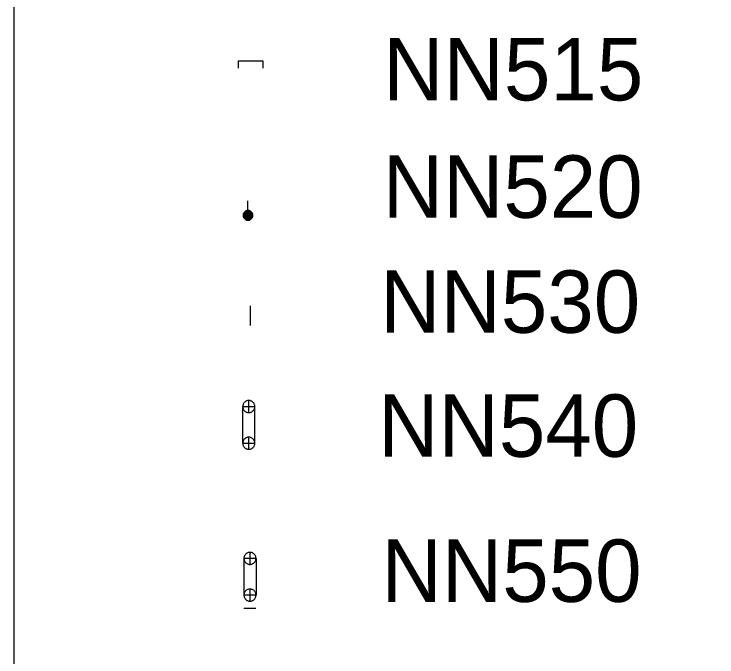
# Model space of a CAD drawing. Extents: x -592841 to -592404, y -1153473 to -1153230.
# Drawn here: x -592679.08 to -592662.21, y -1153397.39 to -1153381.94 of the extents above; entities that cross this region are included whole.
import ezdxf

# ---------------------------------------------------------------- set-up
doc = ezdxf.new("R2010")
doc.units = 0
doc.layers.add('Vrstva 43', color=7, linetype='Continuous')
doc.layers.add('Vrstva 63', color=7, linetype='Continuous')

msp = doc.modelspace()

# ---------------------------------------------------------------- linework, layer by layer
at = {"layer": 'Vrstva 43'}
for points in [[(-592673.703, -1153383.058), (-592673.112, -1153383.058)], [(-592673.703, -1153383.058), (-592673.703, -1153383.235)], [(-592673.112, -1153383.058), (-592673.113, -1153383.236)], [(-592673.468, -1153386.656), (-592673.468, -1153386.421)], [(-592673.351, -1153386.774), (-592673.351, -1153386.761), (-592673.353, -1153386.749), (-592673.357, -1153386.737), (-592673.361, -1153386.726), (-592673.366, -1153386.715), (-592673.373, -1153386.704), (-592673.381, -1153386.695), (-592673.389, -1153386.686), (-592673.399, -1153386.678), (-592673.409, -1153386.672), (-592673.42, -1153386.666), (-592673.431, -1153386.662), (-592673.443, -1153386.658), (-592673.455, -1153386.656), (-592673.468, -1153386.656), (-592673.481, -1153386.656), (-592673.493, -1153386.658), (-592673.505, -1153386.662), (-592673.516, -1153386.666), (-592673.527, -1153386.672), (-592673.537, -1153386.678), (-592673.547, -1153386.686), (-592673.555, -1153386.695), (-592673.563, -1153386.704), (-592673.571, -1153386.715), (-592673.575, -1153386.726), (-592673.58, -1153386.738), (-592673.583, -1153386.749), (-592673.585, -1153386.761), (-592673.585, -1153386.774), (-592673.585, -1153386.786), (-592673.583, -1153386.798), (-592673.58, -1153386.81), (-592673.575, -1153386.822), (-592673.57, -1153386.832), (-592673.563, -1153386.842), (-592673.555, -1153386.852), (-592673.547, -1153386.861), (-592673.537, -1153386.868), (-592673.527, -1153386.876), (-592673.516, -1153386.881), (-592673.505, -1153386.886), (-592673.493, -1153386.888), (-592673.481, -1153386.89), (-592673.468, -1153386.891), (-592673.455, -1153386.891), (-592673.443, -1153386.888), (-592673.431, -1153386.886), (-592673.42, -1153386.881), (-592673.409, -1153386.876), (-592673.399, -1153386.868), (-592673.389, -1153386.861), (-592673.381, -1153386.852), (-592673.373, -1153386.842), (-592673.366, -1153386.833), (-592673.361, -1153386.822), (-592673.357, -1153386.81), (-592673.353, -1153386.798), (-592673.351, -1153386.786), (-592673.351, -1153386.774)], [(-592673.351, -1153386.774), (-592673.351, -1153386.761), (-592673.353, -1153386.749), (-592673.357, -1153386.737), (-592673.361, -1153386.726), (-592673.366, -1153386.715), (-592673.373, -1153386.704), (-592673.381, -1153386.695), (-592673.389, -1153386.686), (-592673.399, -1153386.678), (-592673.409, -1153386.672), (-592673.42, -1153386.666), (-592673.431, -1153386.662), (-592673.443, -1153386.658), (-592673.455, -1153386.656), (-592673.468, -1153386.656), (-592673.481, -1153386.656), (-592673.493, -1153386.658), (-592673.505, -1153386.662), (-592673.516, -1153386.666), (-592673.527, -1153386.672), (-592673.537, -1153386.678), (-592673.547, -1153386.686), (-592673.555, -1153386.695), (-592673.563, -1153386.704), (-592673.571, -1153386.715), (-592673.575, -1153386.726), (-592673.58, -1153386.738), (-592673.583, -1153386.749), (-592673.585, -1153386.761), (-592673.585, -1153386.774), (-592673.585, -1153386.786), (-592673.583, -1153386.798), (-592673.58, -1153386.81), (-592673.575, -1153386.822), (-592673.57, -1153386.832), (-592673.563, -1153386.842), (-592673.555, -1153386.852), (-592673.547, -1153386.861), (-592673.537, -1153386.868), (-592673.527, -1153386.876), (-592673.516, -1153386.881), (-592673.505, -1153386.886), (-592673.493, -1153386.888), (-592673.481, -1153386.89), (-592673.468, -1153386.891), (-592673.455, -1153386.891), (-592673.443, -1153386.888), (-592673.431, -1153386.886), (-592673.42, -1153386.881), (-592673.409, -1153386.876), (-592673.399, -1153386.868), (-592673.389, -1153386.861), (-592673.381, -1153386.852), (-592673.373, -1153386.842), (-592673.366, -1153386.833), (-592673.361, -1153386.822), (-592673.357, -1153386.81), (-592673.353, -1153386.798), (-592673.351, -1153386.786), (-592673.351, -1153386.774)], [(-592673.365, -1153386.774), (-592673.366, -1153386.763), (-592673.367, -1153386.752), (-592673.371, -1153386.742), (-592673.374, -1153386.732), (-592673.379, -1153386.722), (-592673.385, -1153386.713), (-592673.391, -1153386.705), (-592673.399, -1153386.697), (-592673.407, -1153386.69), (-592673.417, -1153386.684), (-592673.426, -1153386.68), (-592673.437, -1153386.676), (-592673.447, -1153386.673), (-592673.457, -1153386.672), (-592673.468, -1153386.671), (-592673.479, -1153386.672), (-592673.49, -1153386.673), (-592673.5, -1153386.676), (-592673.51, -1153386.68), (-592673.519, -1153386.684), (-592673.529, -1153386.691), (-592673.537, -1153386.697), (-592673.545, -1153386.705), (-592673.551, -1153386.713), (-592673.557, -1153386.722), (-592673.563, -1153386.732), (-592673.565, -1153386.742), (-592673.569, -1153386.752), (-592673.57, -1153386.763), (-592673.571, -1153386.774), (-592673.57, -1153386.784), (-592673.569, -1153386.795), (-592673.565, -1153386.806), (-592673.563, -1153386.816), (-592673.557, -1153386.826), (-592673.551, -1153386.834), (-592673.545, -1153386.842), (-592673.537, -1153386.85), (-592673.529, -1153386.857), (-592673.519, -1153386.862), (-592673.51, -1153386.868), (-592673.5, -1153386.871), (-592673.489, -1153386.874), (-592673.479, -1153386.876), (-592673.468, -1153386.876), (-592673.458, -1153386.876), (-592673.447, -1153386.874), (-592673.437, -1153386.871), (-592673.426, -1153386.868), (-592673.417, -1153386.862), (-592673.407, -1153386.856), (-592673.399, -1153386.85), (-592673.391, -1153386.842), (-592673.385, -1153386.834), (-592673.379, -1153386.825), (-592673.374, -1153386.816), (-592673.371, -1153386.806), (-592673.368, -1153386.795), (-592673.367, -1153386.784), (-592673.365, -1153386.774)], [(-592673.38, -1153386.774), (-592673.381, -1153386.764), (-592673.382, -1153386.755), (-592673.385, -1153386.746), (-592673.387, -1153386.738), (-592673.393, -1153386.73), (-592673.397, -1153386.722), (-592673.403, -1153386.714), (-592673.409, -1153386.708), (-592673.417, -1153386.703), (-592673.425, -1153386.698), (-592673.433, -1153386.693), (-592673.441, -1153386.69), (-592673.449, -1153386.688), (-592673.459, -1153386.686), (-592673.469, -1153386.686), (-592673.477, -1153386.686), (-592673.487, -1153386.688), (-592673.495, -1153386.69), (-592673.504, -1153386.693), (-592673.512, -1153386.698), (-592673.519, -1153386.702), (-592673.527, -1153386.708), (-592673.533, -1153386.714), (-592673.539, -1153386.722), (-592673.544, -1153386.73), (-592673.549, -1153386.738), (-592673.551, -1153386.746), (-592673.554, -1153386.755), (-592673.555, -1153386.764), (-592673.556, -1153386.774), (-592673.555, -1153386.783), (-592673.554, -1153386.792), (-592673.551, -1153386.8), (-592673.549, -1153386.81), (-592673.545, -1153386.818), (-592673.539, -1153386.825), (-592673.533, -1153386.832), (-592673.527, -1153386.839), (-592673.519, -1153386.845), (-592673.512, -1153386.85), (-592673.504, -1153386.854), (-592673.495, -1153386.857), (-592673.487, -1153386.86), (-592673.477, -1153386.861), (-592673.469, -1153386.862), (-592673.459, -1153386.861), (-592673.449, -1153386.86), (-592673.441, -1153386.857), (-592673.433, -1153386.854), (-592673.424, -1153386.85), (-592673.417, -1153386.844), (-592673.409, -1153386.839), (-592673.403, -1153386.832), (-592673.397, -1153386.825), (-592673.392, -1153386.818), (-592673.387, -1153386.81), (-592673.385, -1153386.8), (-592673.382, -1153386.792), (-592673.381, -1153386.782), (-592673.38, -1153386.774)], [(-592673.395, -1153386.774), (-592673.396, -1153386.766), (-592673.397, -1153386.758), (-592673.399, -1153386.751), (-592673.401, -1153386.744), (-592673.405, -1153386.737), (-592673.409, -1153386.73), (-592673.414, -1153386.724), (-592673.419, -1153386.719), (-592673.425, -1153386.714), (-592673.432, -1153386.71), (-592673.439, -1153386.706), (-592673.445, -1153386.704), (-592673.453, -1153386.702), (-592673.461, -1153386.701), (-592673.468, -1153386.7), (-592673.475, -1153386.701), (-592673.483, -1153386.702), (-592673.491, -1153386.704), (-592673.497, -1153386.706), (-592673.505, -1153386.71), (-592673.511, -1153386.714), (-592673.517, -1153386.719), (-592673.523, -1153386.724), (-592673.527, -1153386.731), (-592673.532, -1153386.737), (-592673.535, -1153386.744), (-592673.537, -1153386.751), (-592673.539, -1153386.758), (-592673.541, -1153386.766), (-592673.541, -1153386.774), (-592673.541, -1153386.781), (-592673.539, -1153386.788), (-592673.537, -1153386.796), (-592673.535, -1153386.803), (-592673.531, -1153386.81), (-592673.527, -1153386.816), (-592673.523, -1153386.823), (-592673.517, -1153386.828), (-592673.511, -1153386.832), (-592673.505, -1153386.837), (-592673.497, -1153386.84), (-592673.491, -1153386.843), (-592673.483, -1153386.845), (-592673.475, -1153386.846), (-592673.468, -1153386.846), (-592673.461, -1153386.846), (-592673.453, -1153386.845), (-592673.445, -1153386.843), (-592673.439, -1153386.84), (-592673.431, -1153386.837), (-592673.425, -1153386.832), (-592673.419, -1153386.828), (-592673.413, -1153386.822), (-592673.409, -1153386.816), (-592673.405, -1153386.81), (-592673.401, -1153386.803), (-592673.399, -1153386.796), (-592673.397, -1153386.788), (-592673.395, -1153386.781), (-592673.395, -1153386.774)], [(-592673.409, -1153386.774), (-592673.41, -1153386.768), (-592673.411, -1153386.762), (-592673.413, -1153386.756), (-592673.415, -1153386.75), (-592673.417, -1153386.744), (-592673.421, -1153386.739), (-592673.425, -1153386.734), (-592673.429, -1153386.73), (-592673.433, -1153386.726), (-592673.439, -1153386.723), (-592673.445, -1153386.721), (-592673.45, -1153386.718), (-592673.456, -1153386.716), (-592673.462, -1153386.716), (-592673.468, -1153386.715), (-592673.474, -1153386.716), (-592673.48, -1153386.716), (-592673.487, -1153386.718), (-592673.491, -1153386.72), (-592673.497, -1153386.723), (-592673.503, -1153386.726), (-592673.507, -1153386.73), (-592673.511, -1153386.735), (-592673.515, -1153386.739), (-592673.519, -1153386.744), (-592673.521, -1153386.75), (-592673.523, -1153386.756), (-592673.525, -1153386.762), (-592673.526, -1153386.768), (-592673.527, -1153386.774), (-592673.526, -1153386.78), (-592673.525, -1153386.786), (-592673.523, -1153386.792), (-592673.521, -1153386.797), (-592673.519, -1153386.802), (-592673.515, -1153386.808), (-592673.512, -1153386.812), (-592673.507, -1153386.817), (-592673.503, -1153386.82), (-592673.497, -1153386.824), (-592673.491, -1153386.827), (-592673.486, -1153386.829), (-592673.48, -1153386.83), (-592673.474, -1153386.832), (-592673.468, -1153386.832), (-592673.462, -1153386.832), (-592673.456, -1153386.83), (-592673.451, -1153386.829), (-592673.445, -1153386.827), (-592673.439, -1153386.824), (-592673.433, -1153386.82), (-592673.429, -1153386.817), (-592673.425, -1153386.812), (-592673.421, -1153386.808), (-592673.417, -1153386.802), (-592673.415, -1153386.798), (-592673.413, -1153386.792), (-592673.411, -1153386.786), (-592673.41, -1153386.78), (-592673.409, -1153386.774)], [(-592673.425, -1153386.774), (-592673.425, -1153386.769), (-592673.425, -1153386.764), (-592673.427, -1153386.76), (-592673.429, -1153386.756), (-592673.431, -1153386.752), (-592673.433, -1153386.748), (-592673.435, -1153386.744), (-592673.439, -1153386.741), (-592673.443, -1153386.738), (-592673.447, -1153386.736), (-592673.451, -1153386.734), (-592673.455, -1153386.732), (-592673.459, -1153386.731), (-592673.464, -1153386.73), (-592673.469, -1153386.73), (-592673.473, -1153386.73), (-592673.477, -1153386.732), (-592673.481, -1153386.732), (-592673.485, -1153386.734), (-592673.49, -1153386.736), (-592673.493, -1153386.739), (-592673.497, -1153386.741), (-592673.501, -1153386.744), (-592673.503, -1153386.748), (-592673.505, -1153386.752), (-592673.507, -1153386.756), (-592673.51, -1153386.76), (-592673.511, -1153386.764), (-592673.511, -1153386.769), (-592673.511, -1153386.774), (-592673.511, -1153386.778), (-592673.511, -1153386.782), (-592673.509, -1153386.787), (-592673.507, -1153386.791), (-592673.505, -1153386.795), (-592673.503, -1153386.799), (-592673.501, -1153386.802), (-592673.497, -1153386.806), (-592673.493, -1153386.808), (-592673.489, -1153386.811), (-592673.485, -1153386.813), (-592673.481, -1153386.815), (-592673.477, -1153386.816), (-592673.473, -1153386.817), (-592673.468, -1153386.817), (-592673.463, -1153386.817), (-592673.459, -1153386.816), (-592673.455, -1153386.815), (-592673.451, -1153386.813), (-592673.447, -1153386.811), (-592673.443, -1153386.808), (-592673.439, -1153386.806), (-592673.435, -1153386.802), (-592673.433, -1153386.799), (-592673.431, -1153386.795), (-592673.429, -1153386.791), (-592673.427, -1153386.787), (-592673.425, -1153386.782), (-592673.425, -1153386.778), (-592673.425, -1153386.774)], [(-592673.439, -1153386.774), (-592673.439, -1153386.77), (-592673.44, -1153386.768), (-592673.441, -1153386.764), (-592673.442, -1153386.762), (-592673.443, -1153386.76), (-592673.445, -1153386.756), (-592673.447, -1153386.754), (-592673.449, -1153386.752), (-592673.451, -1153386.75), (-592673.453, -1153386.748), (-592673.457, -1153386.748), (-592673.459, -1153386.746), (-592673.462, -1153386.746), (-592673.465, -1153386.745), (-592673.468, -1153386.745), (-592673.471, -1153386.745), (-592673.474, -1153386.746), (-592673.477, -1153386.746), (-592673.48, -1153386.748), (-592673.483, -1153386.748), (-592673.485, -1153386.75), (-592673.487, -1153386.752), (-592673.489, -1153386.754), (-592673.491, -1153386.756), (-592673.493, -1153386.759), (-592673.494, -1153386.762), (-592673.495, -1153386.764), (-592673.496, -1153386.768), (-592673.497, -1153386.771), (-592673.497, -1153386.774), (-592673.497, -1153386.776), (-592673.496, -1153386.78), (-592673.496, -1153386.782), (-592673.494, -1153386.785), (-592673.493, -1153386.788), (-592673.491, -1153386.79), (-592673.489, -1153386.792), (-592673.487, -1153386.795), (-592673.485, -1153386.796), (-592673.483, -1153386.798), (-592673.479, -1153386.8), (-592673.477, -1153386.801), (-592673.474, -1153386.802), (-592673.471, -1153386.802), (-592673.468, -1153386.802), (-592673.465, -1153386.802), (-592673.463, -1153386.802), (-592673.459, -1153386.801), (-592673.457, -1153386.8), (-592673.453, -1153386.798), (-592673.451, -1153386.796), (-592673.449, -1153386.795), (-592673.447, -1153386.792), (-592673.445, -1153386.79), (-592673.443, -1153386.788), (-592673.442, -1153386.785), (-592673.441, -1153386.782), (-592673.44, -1153386.78), (-592673.439, -1153386.776), (-592673.439, -1153386.774)], [(-592673.455, -1153386.774), (-592673.454, -1153386.772), (-592673.455, -1153386.77), (-592673.455, -1153386.769), (-592673.456, -1153386.768), (-592673.456, -1153386.766), (-592673.457, -1153386.766), (-592673.457, -1153386.764), (-592673.459, -1153386.763), (-592673.461, -1153386.762), (-592673.461, -1153386.762), (-592673.463, -1153386.761), (-592673.463, -1153386.76), (-592673.465, -1153386.76), (-592673.467, -1153386.76), (-592673.468, -1153386.76), (-592673.469, -1153386.76), (-592673.471, -1153386.76), (-592673.473, -1153386.76), (-592673.474, -1153386.761), (-592673.475, -1153386.762), (-592673.476, -1153386.762), (-592673.478, -1153386.763), (-592673.479, -1153386.764), (-592673.479, -1153386.766), (-592673.48, -1153386.766), (-592673.481, -1153386.768), (-592673.481, -1153386.769), (-592673.482, -1153386.77), (-592673.482, -1153386.772), (-592673.483, -1153386.774), (-592673.482, -1153386.775), (-592673.481, -1153386.777), (-592673.481, -1153386.778), (-592673.481, -1153386.779), (-592673.48, -1153386.78), (-592673.479, -1153386.782), (-592673.479, -1153386.783), (-592673.478, -1153386.784), (-592673.477, -1153386.784), (-592673.475, -1153386.786), (-592673.473, -1153386.786), (-592673.473, -1153386.786), (-592673.471, -1153386.787), (-592673.47, -1153386.788), (-592673.468, -1153386.788), (-592673.467, -1153386.788), (-592673.465, -1153386.787), (-592673.463, -1153386.786), (-592673.463, -1153386.786), (-592673.461, -1153386.786), (-592673.46, -1153386.784), (-592673.459, -1153386.784), (-592673.457, -1153386.783), (-592673.457, -1153386.782), (-592673.456, -1153386.78), (-592673.455, -1153386.78), (-592673.455, -1153386.778), (-592673.455, -1153386.776), (-592673.454, -1153386.775), (-592673.455, -1153386.774)], [(-592673.411, -1153389.419), (-592673.411, -1153388.951)], [(-592673.595, -1153391.368), (-592673.593, -1153391.384), (-592673.591, -1153391.4), (-592673.587, -1153391.414), (-592673.582, -1153391.428), (-592673.575, -1153391.442), (-592673.567, -1153391.454), (-592673.557, -1153391.466), (-592673.546, -1153391.478), (-592673.535, -1153391.488), (-592673.522, -1153391.495), (-592673.509, -1153391.502), (-592673.493, -1153391.507), (-592673.479, -1153391.512), (-592673.465, -1153391.514), (-592673.449, -1153391.515), (-592673.434, -1153391.514), (-592673.419, -1153391.512), (-592673.404, -1153391.508), (-592673.389, -1153391.502), (-592673.376, -1153391.495), (-592673.364, -1153391.486), (-592673.351, -1153391.477), (-592673.341, -1153391.466), (-592673.331, -1153391.454), (-592673.323, -1153391.442), (-592673.317, -1153391.429), (-592673.311, -1153391.414), (-592673.307, -1153391.399), (-592673.305, -1153391.384), (-592673.304, -1153391.37), (-592673.304, -1153391.354), (-592673.307, -1153391.339), (-592673.311, -1153391.324), (-592673.317, -1153391.31), (-592673.323, -1153391.296), (-592673.331, -1153391.283), (-592673.341, -1153391.272), (-592673.351, -1153391.261), (-592673.363, -1153391.252), (-592673.376, -1153391.243), (-592673.389, -1153391.236), (-592673.405, -1153391.23), (-592673.419, -1153391.227), (-592673.434, -1153391.224), (-592673.449, -1153391.224), (-592673.465, -1153391.224), (-592673.479, -1153391.227), (-592673.493, -1153391.231), (-592673.509, -1153391.236), (-592673.521, -1153391.243), (-592673.535, -1153391.252), (-592673.547, -1153391.26), (-592673.557, -1153391.272), (-592673.567, -1153391.284), (-592673.575, -1153391.297), (-592673.582, -1153391.31), (-592673.587, -1153391.324), (-592673.591, -1153391.339), (-592673.594, -1153391.354), (-592673.595, -1153391.368)], [(-592673.595, -1153391.368), (-592673.304, -1153391.37)], [(-592673.595, -1153392.251), (-592673.595, -1153391.368)], [(-592673.449, -1153391.515), (-592673.449, -1153391.224)], [(-592673.303, -1153392.251), (-592673.304, -1153391.37)], [(-592673.595, -1153392.251), (-592673.593, -1153392.266), (-592673.591, -1153392.282), (-592673.587, -1153392.296), (-592673.582, -1153392.31), (-592673.575, -1153392.324), (-592673.567, -1153392.336), (-592673.557, -1153392.348), (-592673.546, -1153392.36), (-592673.535, -1153392.368), (-592673.521, -1153392.378), (-592673.509, -1153392.384), (-592673.494, -1153392.389), (-592673.479, -1153392.394), (-592673.465, -1153392.396), (-592673.449, -1153392.397), (-592673.433, -1153392.396), (-592673.419, -1153392.394), (-592673.405, -1153392.39), (-592673.389, -1153392.384), (-592673.376, -1153392.377), (-592673.364, -1153392.368), (-592673.352, -1153392.358), (-592673.341, -1153392.348), (-592673.331, -1153392.337), (-592673.323, -1153392.324), (-592673.316, -1153392.31), (-592673.311, -1153392.296), (-592673.307, -1153392.28), (-592673.305, -1153392.266), (-592673.303, -1153392.251), (-592673.304, -1153392.236), (-592673.307, -1153392.22), (-592673.311, -1153392.206), (-592673.317, -1153392.192), (-592673.323, -1153392.178), (-592673.331, -1153392.166), (-592673.341, -1153392.154), (-592673.352, -1153392.143), (-592673.363, -1153392.134), (-592673.376, -1153392.125), (-592673.389, -1153392.118), (-592673.405, -1153392.112), (-592673.419, -1153392.108), (-592673.433, -1153392.106), (-592673.449, -1153392.106), (-592673.465, -1153392.106), (-592673.479, -1153392.108), (-592673.494, -1153392.112), (-592673.508, -1153392.118), (-592673.522, -1153392.124), (-592673.535, -1153392.134), (-592673.547, -1153392.143), (-592673.557, -1153392.154), (-592673.567, -1153392.166), (-592673.575, -1153392.178), (-592673.581, -1153392.192), (-592673.587, -1153392.206), (-592673.591, -1153392.22), (-592673.593, -1153392.236), (-592673.595, -1153392.251)], [(-592673.449, -1153392.397), (-592673.449, -1153392.106)], [(-592673.595, -1153392.251), (-592673.303, -1153392.251)], [(-592673.275, -1153395.018), (-592673.277, -1153395.003), (-592673.279, -1153394.988), (-592673.283, -1153394.974), (-592673.288, -1153394.959), (-592673.295, -1153394.946), (-592673.303, -1153394.933), (-592673.313, -1153394.921), (-592673.324, -1153394.91), (-592673.335, -1153394.9), (-592673.348, -1153394.892), (-592673.362, -1153394.886), (-592673.376, -1153394.88), (-592673.391, -1153394.876), (-592673.405, -1153394.874), (-592673.421, -1153394.873), (-592673.436, -1153394.874), (-592673.451, -1153394.876), (-592673.466, -1153394.88), (-592673.48, -1153394.886), (-592673.493, -1153394.893), (-592673.507, -1153394.9), (-592673.519, -1153394.91), (-592673.529, -1153394.922), (-592673.539, -1153394.933), (-592673.547, -1153394.946), (-592673.553, -1153394.959), (-592673.559, -1153394.974), (-592673.563, -1153394.988), (-592673.565, -1153395.003), (-592673.567, -1153395.018), (-592673.565, -1153395.034), (-592673.563, -1153395.048), (-592673.559, -1153395.063), (-592673.554, -1153395.078), (-592673.547, -1153395.091), (-592673.539, -1153395.104), (-592673.529, -1153395.116), (-592673.519, -1153395.126), (-592673.507, -1153395.136), (-592673.493, -1153395.144), (-592673.48, -1153395.151), (-592673.466, -1153395.156), (-592673.451, -1153395.16), (-592673.436, -1153395.163), (-592673.421, -1153395.164), (-592673.405, -1153395.163), (-592673.391, -1153395.16), (-592673.377, -1153395.156), (-592673.361, -1153395.151), (-592673.348, -1153395.144), (-592673.336, -1153395.136), (-592673.324, -1153395.126), (-592673.313, -1153395.116), (-592673.303, -1153395.104), (-592673.295, -1153395.091), (-592673.288, -1153395.078), (-592673.283, -1153395.063), (-592673.279, -1153395.048), (-592673.277, -1153395.034), (-592673.275, -1153395.018)], [(-592673.421, -1153394.873), (-592673.421, -1153395.164)], [(-592673.275, -1153395.018), (-592673.567, -1153395.018)], [(-592673.567, -1153395.018), (-592673.567, -1153395.9)], [(-592673.275, -1153395.018), (-592673.275, -1153395.9)], [(-592673.275, -1153395.9), (-592673.277, -1153395.885), (-592673.279, -1153395.87), (-592673.283, -1153395.856), (-592673.288, -1153395.841), (-592673.295, -1153395.828), (-592673.303, -1153395.814), (-592673.313, -1153395.803), (-592673.323, -1153395.792), (-592673.335, -1153395.782), (-592673.348, -1153395.775), (-592673.361, -1153395.767), (-592673.376, -1153395.762), (-592673.391, -1153395.758), (-592673.405, -1153395.756), (-592673.421, -1153395.754), (-592673.437, -1153395.756), (-592673.451, -1153395.758), (-592673.466, -1153395.762), (-592673.48, -1153395.767), (-592673.494, -1153395.774), (-592673.507, -1153395.782), (-592673.519, -1153395.792), (-592673.529, -1153395.804), (-592673.539, -1153395.814), (-592673.547, -1153395.828), (-592673.554, -1153395.841), (-592673.559, -1153395.856), (-592673.563, -1153395.87), (-592673.566, -1153395.885), (-592673.567, -1153395.9), (-592673.565, -1153395.916), (-592673.563, -1153395.93), (-592673.559, -1153395.945), (-592673.553, -1153395.96), (-592673.547, -1153395.973), (-592673.539, -1153395.986), (-592673.529, -1153395.998), (-592673.519, -1153396.008), (-592673.507, -1153396.018), (-592673.493, -1153396.026), (-592673.481, -1153396.033), (-592673.466, -1153396.038), (-592673.451, -1153396.042), (-592673.436, -1153396.045), (-592673.421, -1153396.046), (-592673.406, -1153396.045), (-592673.391, -1153396.042), (-592673.376, -1153396.038), (-592673.362, -1153396.033), (-592673.348, -1153396.026), (-592673.335, -1153396.018), (-592673.323, -1153396.008), (-592673.313, -1153395.998), (-592673.303, -1153395.986), (-592673.295, -1153395.973), (-592673.289, -1153395.96), (-592673.283, -1153395.945), (-592673.279, -1153395.93), (-592673.277, -1153395.916), (-592673.275, -1153395.9)], [(-592673.421, -1153395.754), (-592673.421, -1153396.046)], [(-592673.275, -1153395.9), (-592673.567, -1153395.9)], [(-592673.571, -1153396.214), (-592673.277, -1153396.214)]]:
    msp.add_lwpolyline(points, dxfattribs=at)
at = {"layer": 'Vrstva 63'}
msp.add_lwpolyline([(-592679.084, -1153338.599), (-592600.649, -1153338.599), (-592600.649, -1153436.347), (-592679.084, -1153436.347)], close=True, dxfattribs=at)

# ---------------------------------------------------------------- texts
for s, p in [('NN515', (-592670.219, -1153384.011)), ('NN520', (-592670.234, -1153386.833)), ('NN530', (-592670.294, -1153389.597)), ('NN540', (-592670.341, -1153392.577)), ('NN550', (-592670.26, -1153396.063))]:
    msp.add_text(s, height=1.5, dxfattribs=at).set_placement(p)

doc.saveas('drawing.dxf')
